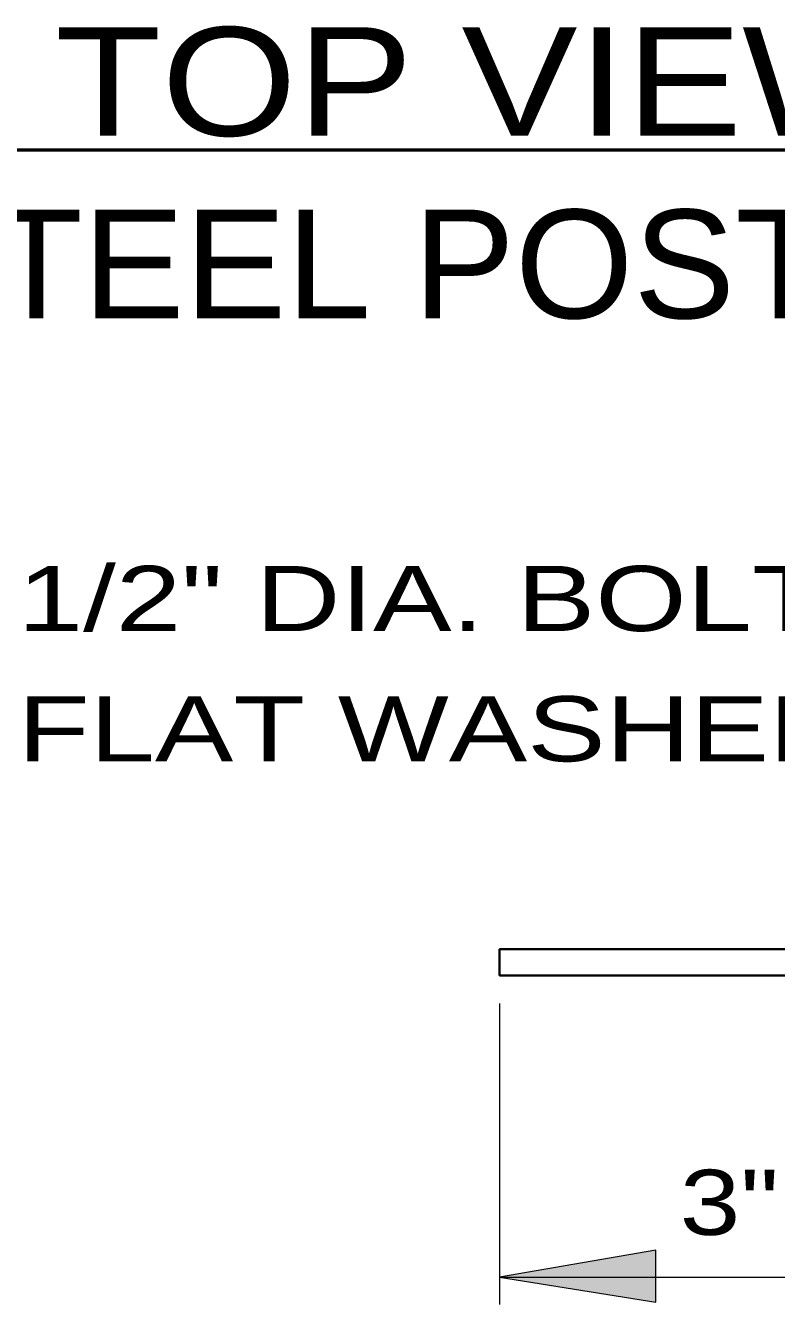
# Model space of a CAD drawing. Extents: x 5332.5 to 5339, y 1824.9 to 1835.1.
# Drawn here: x 5333.42 to 5334.112, y 1826.776 to 1827.953 of the extents above; entities that cross this region are included whole.
import ezdxf
from ezdxf.enums import TextEntityAlignment as Align

# ---------------------------------------------------------------- set-up
doc = ezdxf.new("R2010")
doc.units = 0
doc.header["$LTSCALE"] = 0.024
for name, color, linetype, lineweight in [('1', 7, 'Continuous', 35), ('10', 7, 'Continuous', 13), ('12', 7, 'Continuous', 53)]:
    doc.layers.add(name, color=color, linetype=linetype, lineweight=lineweight)

msp = doc.modelspace()

# ---------------------------------------------------------------- hatches: boundary and pattern name
at = {"layer": '10'}
msp.add_hatch(color=256, dxfattribs=at).paths.add_polyline_path([(5334.001, 1826.778), (5334.001, 1826.826), (5333.857, 1826.801)])
msp.add_hatch(color=256, dxfattribs=at).paths.add_polyline_path([(5334.001, 1826.778), (5334.001, 1826.826), (5333.857, 1826.801)])
msp.add_hatch(color=256, dxfattribs=at).paths.add_polyline_path([(5334.001, 1826.778), (5334.001, 1826.826), (5333.857, 1826.801)])
msp.add_hatch(color=256, dxfattribs=at).paths.add_polyline_path([(5334.001, 1826.778), (5334.001, 1826.826), (5333.857, 1826.801)])
msp.add_hatch(color=256, dxfattribs=at).paths.add_polyline_path([(5334.001, 1826.778), (5334.001, 1826.826), (5333.857, 1826.801)])
msp.add_hatch(color=256, dxfattribs=at).paths.add_polyline_path([(5334.001, 1826.778), (5334.001, 1826.826), (5333.857, 1826.801)])
msp.add_hatch(color=256, dxfattribs=at).paths.add_polyline_path([(5334.001, 1826.778), (5334.001, 1826.826), (5333.857, 1826.801)])
msp.add_hatch(color=256, dxfattribs=at).paths.add_polyline_path([(5334.001, 1826.778), (5334.001, 1826.826), (5333.857, 1826.801)])
msp.add_hatch(color=256, dxfattribs=at).paths.add_polyline_path([(5334.001, 1826.778), (5334.001, 1826.826), (5333.857, 1826.801)])
msp.add_hatch(color=256, dxfattribs=at).paths.add_polyline_path([(5334.001, 1826.778), (5334.001, 1826.826), (5333.857, 1826.801)])
msp.add_hatch(color=256, dxfattribs=at).paths.add_polyline_path([(5334.001, 1826.778), (5334.001, 1826.826), (5333.857, 1826.801)])

# ---------------------------------------------------------------- linework, layer by layer
at = {"layer": '1'}
msp.add_line((5337.53, 1827.103), (5333.857, 1827.103), dxfattribs=at)
msp.add_lwpolyline([(5337.53, 1827.103), (5333.857, 1827.103), (5333.857, 1827.079), (5334.26, 1827.079)], dxfattribs=at)
msp.add_lwpolyline([(5337.53, 1827.103), (5333.857, 1827.103), (5333.857, 1827.079), (5334.26, 1827.079)], dxfattribs=at)
msp.add_lwpolyline([(5337.53, 1827.103), (5333.857, 1827.103), (5333.857, 1827.079), (5334.26, 1827.079)], dxfattribs=at)
msp.add_lwpolyline([(5337.53, 1827.103), (5333.857, 1827.103), (5333.857, 1827.079), (5334.26, 1827.079)], dxfattribs=at)
msp.add_lwpolyline([(5337.53, 1827.103), (5333.857, 1827.103), (5333.857, 1827.079), (5334.26, 1827.079)], dxfattribs=at)
msp.add_lwpolyline([(5337.53, 1827.103), (5333.857, 1827.103), (5333.857, 1827.079), (5334.26, 1827.079)], dxfattribs=at)
msp.add_lwpolyline([(5337.53, 1827.103), (5333.857, 1827.103), (5333.857, 1827.079), (5334.26, 1827.079)], dxfattribs=at)
msp.add_lwpolyline([(5337.53, 1827.103), (5333.857, 1827.103), (5333.857, 1827.079), (5334.26, 1827.079)], dxfattribs=at)
msp.add_lwpolyline([(5337.53, 1827.103), (5333.857, 1827.103), (5333.857, 1827.079), (5334.26, 1827.079)], dxfattribs=at)
msp.add_lwpolyline([(5337.53, 1827.103), (5333.857, 1827.103), (5333.857, 1827.079), (5334.26, 1827.079)], dxfattribs=at)
msp.add_lwpolyline([(5337.53, 1827.103), (5333.857, 1827.103), (5333.857, 1827.079), (5334.26, 1827.079)], dxfattribs=at)
msp.add_lwpolyline([(5337.53, 1827.103), (5333.857, 1827.103), (5333.857, 1827.079), (5334.26, 1827.079)], dxfattribs=at)
msp.add_lwpolyline([(5337.53, 1827.103), (5333.857, 1827.103), (5333.857, 1827.079), (5334.26, 1827.079)], dxfattribs=at)
at = {"layer": '10'}
for p, q in [((5333.857, 1827.053), (5333.857, 1826.776)), ((5333.857, 1827.053), (5333.857, 1826.776)), ((5333.857, 1827.053), (5333.857, 1826.776)), ((5333.857, 1827.053), (5333.857, 1826.776)), ((5333.857, 1827.053), (5333.857, 1826.776)), ((5333.857, 1827.053), (5333.857, 1826.776)), ((5333.857, 1827.053), (5333.857, 1826.776)), ((5333.857, 1827.053), (5333.857, 1826.776)), ((5333.857, 1827.053), (5333.857, 1826.776)), ((5333.857, 1827.053), (5333.857, 1826.776)), ((5333.857, 1827.053), (5333.857, 1826.776)), ((5333.857, 1826.801), (5334.26, 1826.801)), ((5333.857, 1826.801), (5334.26, 1826.801)), ((5333.857, 1826.801), (5334.26, 1826.801)), ((5333.857, 1826.801), (5334.26, 1826.801)), ((5333.857, 1826.801), (5334.26, 1826.801)), ((5333.857, 1826.801), (5334.26, 1826.801)), ((5333.857, 1826.801), (5334.26, 1826.801)), ((5333.857, 1826.801), (5334.26, 1826.801)), ((5333.857, 1826.801), (5334.26, 1826.801)), ((5333.857, 1826.801), (5334.26, 1826.801)), ((5333.857, 1826.801), (5334.26, 1826.801))]:
    msp.add_line(p, q, dxfattribs=at)
msp.add_lwpolyline([(5334.001, 1826.778), (5334.001, 1826.826), (5333.857, 1826.801)], close=True, dxfattribs=at)
msp.add_lwpolyline([(5334.001, 1826.778), (5334.001, 1826.826), (5333.857, 1826.801)], close=True, dxfattribs=at)
msp.add_lwpolyline([(5334.001, 1826.778), (5334.001, 1826.826), (5333.857, 1826.801)], close=True, dxfattribs=at)
msp.add_lwpolyline([(5334.001, 1826.778), (5334.001, 1826.826), (5333.857, 1826.801)], close=True, dxfattribs=at)
msp.add_lwpolyline([(5334.001, 1826.778), (5334.001, 1826.826), (5333.857, 1826.801)], close=True, dxfattribs=at)
msp.add_lwpolyline([(5334.001, 1826.778), (5334.001, 1826.826), (5333.857, 1826.801)], close=True, dxfattribs=at)
msp.add_lwpolyline([(5334.001, 1826.778), (5334.001, 1826.826), (5333.857, 1826.801)], close=True, dxfattribs=at)
msp.add_lwpolyline([(5334.001, 1826.778), (5334.001, 1826.826), (5333.857, 1826.801)], close=True, dxfattribs=at)
msp.add_lwpolyline([(5334.001, 1826.778), (5334.001, 1826.826), (5333.857, 1826.801)], close=True, dxfattribs=at)
msp.add_lwpolyline([(5334.001, 1826.778), (5334.001, 1826.826), (5333.857, 1826.801)], close=True, dxfattribs=at)
msp.add_lwpolyline([(5334.001, 1826.778), (5334.001, 1826.826), (5333.857, 1826.801)], close=True, dxfattribs=at)
at = {"layer": '12'}
msp.add_line((5332.522, 1827.839), (5334.237, 1827.839), dxfattribs=at)

# ---------------------------------------------------------------- texts
for s, width, p in [("DETAIL 'B' - TOP VIEW", 1.2, (5333.381, 1827.852)), ('(TUBULAR STEEL POST)', 1.05, (5333.3795, 1827.684))]:
    msp.add_text(s, height=0.1, dxfattribs=dict(at, width=width)).set_placement(p, align=Align.CENTER)
for s, width, p in [('1/2" DIA. BOLT WITH LOCK, NUTS,', 1.35, (5333.413, 1827.396)), ('FLAT WASHERS (S.S. TYPE 304)', 1.35, (5333.413, 1827.276)), ('3"', 1.25, (5334.023, 1826.84))]:
    msp.add_text(s, height=0.06, dxfattribs=dict(at, width=width)).set_placement(p)

doc.saveas('drawing.dxf')
